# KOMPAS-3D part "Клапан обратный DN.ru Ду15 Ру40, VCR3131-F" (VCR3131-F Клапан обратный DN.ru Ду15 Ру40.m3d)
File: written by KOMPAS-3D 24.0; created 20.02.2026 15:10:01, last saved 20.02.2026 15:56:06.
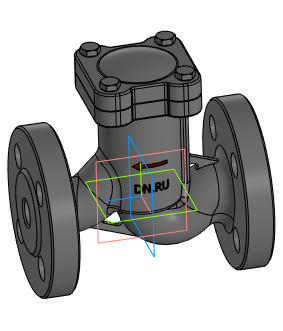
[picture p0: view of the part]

Document properties: Автор: R2D2; Полное имя файла: VCR3131-F Клапан обратный DN.ru Ду15 Ру40.cdw; Организация: DN.ru

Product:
- Body: Тело 3  | qty 1
    Масса: 3.336756
- Part/product: Клапан обратный DN.ru Ду15 Ру40  | designation VCR3131-F
    Масса: 2.8
    Раздел спецификации: Прочие изделия
    Форматы листов документа: A3
    Примечание: D100-04036
    additional columns: D100-04036

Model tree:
1. Операция без истории:1

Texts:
  VCR3131-F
